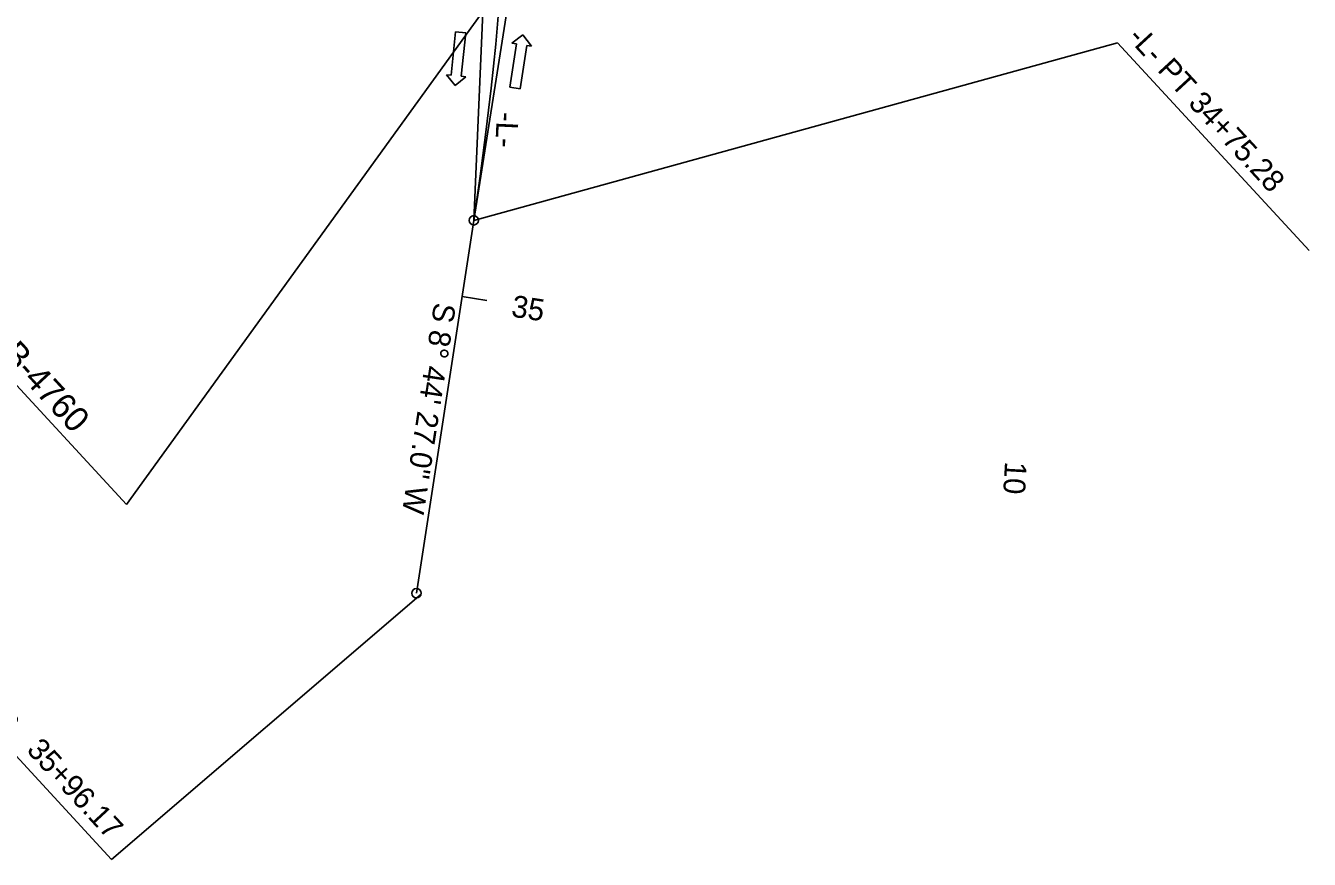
# Model space of a CAD drawing. Extents: x 1702862 to 1704514, y 793768 to 796215.
# Drawn here: x 1703833.9 to 1704245.2, y 793768 to 794035 of the extents above; entities that cross this region are included whole.
import ezdxf

# ---------------------------------------------------------------- set-up
doc = ezdxf.new("R2010")
doc.units = 0
for name, color, linetype in [('Prop DSN Text', 7, 'Continuous'), ('Prop Horizontal Alignment', 7, 'Continuous'), ('Prop Horizontal Alignment Direction Label', 7, 'Continuous'), ('Prop Horizontal Alignment Station Label', 7, 'Continuous'), ('Prop Horizontal Alignment Tick Label', 7, 'Continuous'), ('Prop Horizontal Alignment Tick Large', 7, 'Continuous'), ('Prop Lane Arrow CELL', 7, 'Continuous'), ('Prop Lane Lines', 7, 'Continuous'), ('Prop Leader Line Medium', 7, 'Continuous')]:
    doc.layers.add(name, color=color, linetype=linetype)

msp = doc.modelspace()

# ---------------------------------------------------------------- linework, layer by layer
at = {"layer": 'Prop Horizontal Alignment'}
msp.add_line((1703977.5, 793972.68), (1703959.13, 793853.2), dxfattribs=at)
msp.add_arc((1702989.11, 794124.65), 1000, 351.25916, 42.70907, dxfattribs=at)
at = {"layer": 'Prop Horizontal Alignment Station Label'}
for p, q in [((1703977.5, 793972.68), (1704183.79, 794029.59)), ((1704183.79, 794029.59), (1704245.2, 793963.06)), ((1703960.61, 793852.97), (1703861.43, 793767.97)), ((1703800.56, 793833.92), (1703861.43, 793767.97))]:
    msp.add_line(p, q, dxfattribs=at)
for centre in [(1703977.5, 793972.68), (1703959.13, 793853.2)]:
    msp.add_circle(centre, 1.5, dxfattribs=at)
at = {"layer": 'Prop Horizontal Alignment Tick Large'}
msp.add_line((1703973.74, 793948.25), (1703981.65, 793947.03), dxfattribs=at)
at = {"layer": 'Prop Lane Arrow CELL'}
for p, q in [((1703970.23, 794019.17), (1703971.68, 794033.09)), ((1703971.68, 794033.09), (1703974.97, 794032.75)), ((1703974.97, 794032.75), (1703973.51, 794018.83)), ((1703989.73, 794029.42), (1703993.28, 794032.06)), ((1703993.28, 794032.06), (1703995.96, 794028.46)), ((1703989.06, 794015.36), (1703991.22, 794029.19)), ((1703991.22, 794029.19), (1703989.73, 794029.42)), ((1703994.48, 794028.69), (1703992.33, 794014.85)), ((1703995.96, 794028.46), (1703994.48, 794028.69)), ((1703971.59, 794015.86), (1703968.74, 794019.33)), ((1703968.74, 794019.33), (1703970.23, 794019.17)), ((1703975, 794018.67), (1703971.59, 794015.86)), ((1703973.51, 794018.83), (1703975, 794018.67)), ((1703992.33, 794014.85), (1703989.06, 794015.36))]:
    msp.add_line(p, q, dxfattribs=at)
at = {"layer": 'Prop Lane Lines'}
for p in [(1703980.78, 794048.9), (1703989.31, 794047.5)]:
    msp.add_line(p, (1703977.5, 793972.68), dxfattribs=at)
at = {"layer": 'Prop Leader Line Medium'}
for p in [(1703986.13, 794047.45), (1703754.24, 794003.01)]:
    msp.add_line(p, (1703866.27, 793881.64), dxfattribs=at)

# ---------------------------------------------------------------- texts
at = {"layer": 'Prop DSN Text'}
msp.add_text('END TIP PROJECT B-4760', height=8, rotation=312.7091, dxfattribs=at).set_placement((1703759.29, 794001.5))
at = {"layer": 'Prop Horizontal Alignment Direction Label'}
for s, rotation, p in [('-L-', 267.3709, (1703984.92, 794007.51)), ('S 8%%d 44\' 27.0" W', 261.2592, (1703964.88, 793946.61))]:
    msp.add_text(s, height=7, rotation=rotation, dxfattribs=at).set_placement(p)
at = {"layer": 'Prop Horizontal Alignment Station Label'}
for s, p in [('-L- PT 34+75.28', (1704186.72, 794031)), ('POT Sta.  35+96.17', (1703804.31, 793834.88))]:
    msp.add_text(s, height=7, rotation=312.7091, dxfattribs=at).set_placement(p)
at = {"layer": 'Prop Horizontal Alignment Tick Label'}
for s, rotation, p in [('35', 351.2592, (1703989.28, 793941.88)), ('10', 266.6143, (1704147.72, 793895.51))]:
    msp.add_text(s, height=7, rotation=rotation, dxfattribs=at).set_placement(p)

doc.saveas('drawing.dxf')
